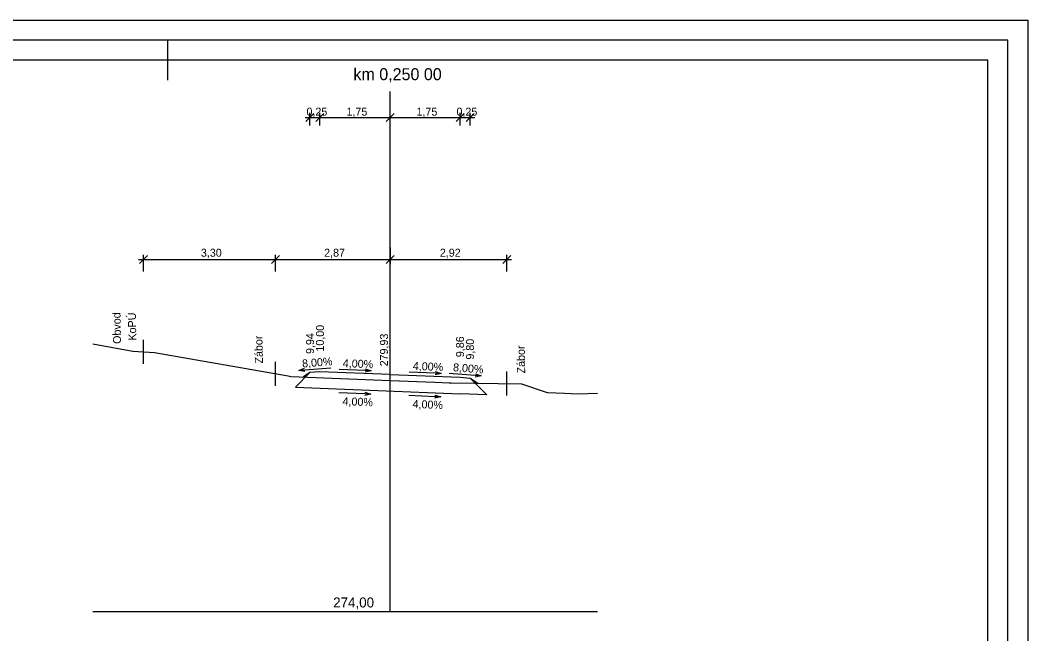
# Model space of a CAD drawing. Extents: x -761098.2 to -761034.2, y -1047998.6 to -1047967.9.
# Drawn here: x -761059.34 to -761034.15, y -1047983.28 to -1047967.93 of the extents above; entities that cross this region are included whole.
import ezdxf

# ---------------------------------------------------------------- set-up
doc = ezdxf.new("R2010")
doc.units = 0
for name, color, linetype in [('C3D-KORIDOR-SPOJNICE', 7, 'Continuous'), ('C3D-POPIS', 7, 'Continuous'), ('C3D-PR-POPIS-TEREN', 7, 'Continuous'), ('C3D-PR-TEREN', 7, 'Continuous'), ('C3D-ZOBPR-NADPIS', 7, 'Continuous'), ('C3D-ZOBPR-OSY', 7, 'Continuous'), ('C3D-ZOBPR-OSY-NADPIS', 7, 'Continuous'), ('Default', 7, 'Continuous'), ('U_formát', 7, 'Continuous'), ('U_rozvržení_rámeček', 7, 'Continuous'), ('Z_Pomocná', 7, 'Continuous')]:
    doc.layers.add(name, color=color, linetype=linetype)

# ---------------------------------------------------------------- blocks, each defined once
blk = doc.blocks.new('_Oblique')
at = {"layer": 'Default'}
blk.add_line((-0.5, -0.5), (0.5, 0.5), dxfattribs=at)
blk = doc.blocks.new('_Open30')
at = {"layer": 'Default'}
for p, q in [((-1, 0.27), (0, 0)), ((0, 0), (-1, -0.27)), ((0, 0), (-1, 0))]:
    blk.add_line(p, q, dxfattribs=at)
blk = doc.blocks.new('U1096')
at = {"layer": 'Default'}
blk.add_line((-210, 0), (-210, -10), dxfattribs=at)
blk.add_lwpolyline([(0, -297), (0, 0), (-630, 0), (-630, -297)], close=True, dxfattribs=at)
at = {"layer": 'U_formát'}
for points in [[(-635, 5), (5, 5), (5, -302), (-635, -302)], [(-5, -292), (-5, -5), (-625, -5), (-625, -292)]]:
    blk.add_lwpolyline(points, close=True, dxfattribs=at)

msp = doc.modelspace()

# ---------------------------------------------------------------- linework, layer by layer
at = {"layer": 'C3D-KORIDOR-SPOJNICE'}
for p, q in [((-761052.093, -1047976.741), (-761052.459, -1047977.107)), ((-761052.093, -1047976.741), (-761052.258, -1047976.851)), ((-761051.843, -1047976.721), (-761052.093, -1047976.741)), ((-761050.093, -1047976.791), (-761051.843, -1047976.721)), ((-761050.093, -1047976.791), (-761048.343, -1047976.861)), ((-761048.343, -1047976.861), (-761048.093, -1047976.881)), ((-761048.093, -1047976.881), (-761047.677, -1047977.298)), ((-761048.093, -1047976.881), (-761047.899, -1047977.011)), ((-761052.459, -1047977.107), (-761048.343, -1047977.271)), ((-761047.677, -1047977.298), (-761048.343, -1047977.271))]:
    msp.add_line(p, q, dxfattribs=at)
at = {"layer": 'C3D-POPIS'}
for p, q in [((-761052.213, -1047970.367), (-761049.973, -1047970.367)), ((-761052.093, -1047970.567), (-761052.093, -1047970.247)), ((-761051.843, -1047970.567), (-761051.843, -1047970.247)), ((-761050.213, -1047970.367), (-761047.973, -1047970.367)), ((-761050.093, -1047970.567), (-761050.093, -1047970.247)), ((-761048.343, -1047970.567), (-761048.343, -1047970.247)), ((-761048.093, -1047970.567), (-761048.093, -1047970.247))]:
    msp.add_line(p, q, dxfattribs=at)
for points in [[(-761052.224, -1047976.677), (-761051.576, -1047976.625)], [(-761050.716, -1047976.691), (-761051.365, -1047976.665)], [(-761048.966, -1047976.761), (-761049.615, -1047976.735)], [(-761047.963, -1047976.817), (-761048.611, -1047976.765)], [(-761050.723, -1047977.276), (-761051.372, -1047977.25)], [(-761048.973, -1047977.346), (-761049.622, -1047977.32)]]:
    msp.add_lwpolyline(points, dxfattribs=at)
at = {"layer": 'C3D-PR-TEREN'}
msp.add_lwpolyline([(-761057.524, -1047976.024), (-761056.525, -1047976.211), (-761055.98, -1047976.243), (-761052.636, -1047976.827), (-761052.576, -1047976.839), (-761050.093, -1047976.938), (-761048.973, -1047976.982), (-761048.614, -1047976.999), (-761048.566, -1047977.003), (-761046.808, -1047977.024), (-761046.163, -1047977.241), (-761045.731, -1047977.257), (-761045.402, -1047977.274), (-761044.909, -1047977.258)], dxfattribs=at)
at = {"layer": 'C3D-ZOBPR-OSY'}
for p, q in [((-761050.093, -1047982.717), (-761050.093, -1047969.717)), ((-761057.524, -1047982.717), (-761044.909, -1047982.717))]:
    msp.add_line(p, q, dxfattribs=at)
at = {"layer": 'Default'}
for p, q in [((-761050.093, -1047973.616), (-761050.093, -1047974.036)), ((-761050.093, -1047973.616), (-761050.093, -1047974.036)), ((-761056.377, -1047973.916), (-761052.839, -1047973.916)), ((-761056.257, -1047974.216), (-761056.257, -1047973.796)), ((-761053.079, -1047973.916), (-761049.973, -1047973.916)), ((-761052.959, -1047974.216), (-761052.959, -1047973.796)), ((-761052.959, -1047974.216), (-761052.959, -1047973.796)), ((-761050.213, -1047973.916), (-761047.057, -1047973.916)), ((-761047.177, -1047974.216), (-761047.177, -1047973.796))]:
    msp.add_line(p, q, dxfattribs=at)
at = {"layer": 'Z_Pomocná'}
for points in [[(-761056.257, -1047976.527), (-761056.257, -1047976.227), (-761056.257, -1047975.927)], [(-761052.959, -1047977.071), (-761052.959, -1047976.771), (-761052.959, -1047976.471)], [(-761047.177, -1047977.32), (-761047.177, -1047977.02), (-761047.177, -1047976.72)]]:
    msp.add_lwpolyline(points, dxfattribs=at)

# ---------------------------------------------------------------- block references
at = {"layer": 'C3D-POPIS'}
for name, p, xscale, yscale, rotation in [('_Oblique', (-761052.093, -1047970.367), 0.2, 0.20000000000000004, 180), ('_Oblique', (-761051.843, -1047970.367), 0.2, 0.20000000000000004, 180), ('_Oblique', (-761050.093, -1047970.367), 0.2, 0.20000000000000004, 180), ('_Open30', (-761052.373, -1047976.689), 0.14999999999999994, 0.14999999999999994, -175.4260787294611), ('_Open30', (-761050.566, -1047976.697), 0.15000000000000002, 0.15000000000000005, -2.290610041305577), ('_Open30', (-761048.816, -1047976.767), 0.15000000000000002, 0.15000000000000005, -2.290610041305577), ('_Open30', (-761047.814, -1047976.829), 0.15, 0.15, -4.573921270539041), ('_Open30', (-761050.573, -1047977.282), 0.15000000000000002, 0.15000000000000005, -2.290610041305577), ('_Open30', (-761048.823, -1047977.352), 0.15000000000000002, 0.15000000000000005, -2.290610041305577)]:
    msp.add_blockref(name, p, dxfattribs=dict(at, xscale=xscale, yscale=yscale, rotation=rotation))
at = {"layer": 'C3D-POPIS', "xscale": 0.2, "yscale": 0.20000000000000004}
for p in [(-761050.093, -1047970.367), (-761048.343, -1047970.367), (-761048.093, -1047970.367)]:
    msp.add_blockref('_Oblique', p, dxfattribs=at)
at = {"layer": 'Default', "xscale": 0.2, "yscale": 0.20000000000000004, "rotation": 180}
for p in [(-761056.257, -1047973.916), (-761052.959, -1047973.916), (-761050.093, -1047973.916)]:
    msp.add_blockref('_Oblique', p, dxfattribs=at)
at = {"layer": 'Default', "xscale": 0.2, "yscale": 0.20000000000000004}
for p in [(-761052.959, -1047973.916), (-761050.093, -1047973.916), (-761047.177, -1047973.916)]:
    msp.add_blockref('_Oblique', p, dxfattribs=at)
at = {"layer": 'U_rozvržení_rámeček', "xscale": 0.1, "yscale": 0.10000000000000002}
msp.add_blockref('U1096', (-761034.651, -1047968.429), dxfattribs=at)

# ---------------------------------------------------------------- texts
at = {"layer": 'C3D-POPIS'}
for s, p in [('0,25', (-761052.181, -1047970.318)), ('1,75', (-761051.181, -1047970.318)), ('1,75', (-761049.431, -1047970.318)), ('0,25', (-761048.431, -1047970.318))]:
    msp.add_text(s, height=0.2, dxfattribs=at).set_placement(p)
for s, rotation, p in [('9,94', 90, (-761051.993, -1047976.278)), ('10,00', 90, (-761051.743, -1047976.218)), ('279,93', 90, (-761050.143, -1047976.588)), ('279,93', 90, (-761050.143, -1047976.588)), ('9,86', 90, (-761048.243, -1047976.358)), ('9,80', 90, (-761047.993, -1047976.418)), ('8,00%', 4.5837, (-761052.282, -1047976.618)), ('4,00%', 357.7082, (-761051.276, -1047976.606)), ('4,00%', 357.7082, (-761049.526, -1047976.676)), ('8,00%', 355.4163, (-761048.523, -1047976.708)), ('4,00%', 357.7094, (-761051.282, -1047977.557)), ('4,00%', 357.7094, (-761049.532, -1047977.627))]:
    msp.add_text(s, height=0.2, rotation=rotation, dxfattribs=at).set_placement(p)
at = {"layer": 'C3D-PR-POPIS-TEREN'}
for s, p in [('Obvod ', (-761056.815, -1047976.024)), ('KoPÚ', (-761056.433, -1047975.94)), ('Zábor', (-761053.269, -1047976.516)), ('Zábor', (-761046.713, -1047976.763))]:
    msp.add_text(s, height=0.2, rotation=91.1271, dxfattribs=at).set_placement(p)
at = {"layer": 'C3D-ZOBPR-NADPIS'}
msp.add_text('km 0,250 00', height=0.3, rotation=360, dxfattribs=at).set_placement((-761051.008, -1047969.43))
at = {"layer": 'C3D-ZOBPR-OSY-NADPIS'}
msp.add_text('274,00', height=0.25, rotation=360, dxfattribs=at).set_placement((-761051.514, -1047982.618))
at = {"layer": 'Default'}
for s, p in [('3,30', (-761054.82, -1047973.846)), ('2,87', (-761051.739, -1047973.846)), ('2,92', (-761048.847, -1047973.846))]:
    msp.add_text(s, height=0.2, dxfattribs=at).set_placement(p)

doc.saveas('drawing.dxf')
